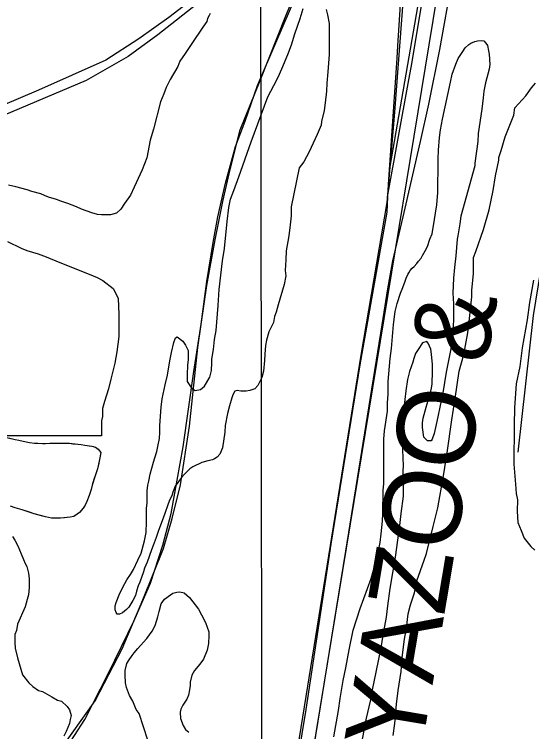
# Model space of a CAD drawing. Extents: x 3313442 to 3351311, y 721974 to 747360.
# Drawn here: x 3327806 to 3328357, y 731523 to 732286 of the extents above; entities that cross this region are included whole.
import ezdxf

# ---------------------------------------------------------------- set-up
doc = ezdxf.new("R2010")
doc.units = 0
for name, color, linetype in [('V-GRID-MAJR', 7, 'Continuous'), ('V-RAIL-IDEN', 7, 'Continuous'), ('V-RAIL-TRAK', 7, 'Continuous'), ('V-ROAD-CNTR', 7, 'Continuous'), ('V-SITE-VEGE', 7, 'Continuous'), ('V-TOPO-SHOR', 7, 'Continuous')]:
    doc.layers.add(name, color=color, linetype=linetype)

msp = doc.modelspace()

# ---------------------------------------------------------------- linework, layer by layer
at = {"layer": 'V-GRID-MAJR'}
msp.add_spline([(3328075.07, 727366.28), (3328067.14, 733424.95), (3328059.2, 739486.71), (3328051.27, 745548.49), (3328051.26, 745551.55)], degree=3, dxfattribs=at)
at = {"layer": 'V-RAIL-TRAK'}
for points in [[(3328203.52, 732092.24), (3328226.38, 732216.75), (3328228.79, 732229.89), (3328244.41, 732323.62), (3328261.52, 732426.58), (3328323.27, 732818.5), (3328429.42, 733429.55), (3328523.11, 733982.36), (3328555.08, 734220.1)], [(3328500.98, 734062.08), (3328491.15, 734030.23), (3328478.19, 734001.71), (3328469.68, 733983.34), (3328457.58, 733940.94), (3328295.7, 733004.83), (3328243.2, 732687.44), (3328233.88, 732532.71), (3328228.65, 732476.24), (3328224.01, 732410.03), (3328223.76, 732406.49), (3328219.24, 732330.46), (3328214.34, 732252.95), (3328213.43, 732239.7)], [(3328193.53, 732625.7), (3328177.22, 732567.4), (3328169.07, 732540.83), (3328156.85, 732510.58), (3328143.9, 732481.07), (3328134.65, 732462.26), (3328103.21, 732412.1), (3328071.41, 732367.84), (3328040.36, 732333.56), (3328005.63, 732301.12), (3327959.07, 732264.63), (3327927.3, 732241.42), (3327882.61, 732216.01), (3327776.62, 732171.47), (3327637.03, 732113.33), (3327497.8, 732056.29), (3327254.9, 731954.47)], [(3327916.04, 730340.51), (3327940.55, 730453.8), (3327956.49, 730526.28), (3327968.38, 730580.36), (3327984, 730670.04), (3328012.27, 730843.85), (3328056.88, 731105.86), (3328114.88, 731442.42), (3328159.14, 731715.13), (3328197.82, 731956.11), (3328203.77, 731994.12), (3328209.35, 732024.01), (3328220.11, 732070.88), (3328238.67, 732150.95), (3328247.57, 732190.8), (3328259.09, 732249.11), (3328272.47, 732322.54), (3328282.13, 732380.48), (3328307.79, 732543.91)], [(3327859.42, 731501.7), (3327881.24, 731536), (3327906.4, 731585.06), (3327933.78, 731641.13), (3327951.18, 731680.98), (3327964.15, 731721.56), (3327973.05, 731755.14), (3327986.05, 731825.99), (3327997.23, 731906.44), (3328005.04, 731956.63), (3328011, 732002.03), (3328018.07, 732043.73), (3328022.9, 732071.03), (3328031.06, 732106.83), (3328041.81, 732145.94), (3328051.82, 732172.87), (3328065.15, 732210.87), (3328084.77, 732256.25), (3328106.98, 732308.27)], [(3328213.43, 732239.7), (3328204.2, 732105.32), (3328203.52, 732092.24)], [(3328203.52, 732092.24), (3328202.68, 732075.79), (3328174.06, 731913.42), (3328143.19, 731722.63), (3328116.4, 731546.6), (3328078.46, 731315.59), (3327969.89, 730676.8), (3327964.29, 730653.18)]]:
    msp.add_lwpolyline(points, dxfattribs=at)
at = {"layer": 'V-ROAD-CNTR'}
for points in [[(3327896.37, 730170.39), (3328023.81, 730890.68), (3328416, 733278.4), (3328655.93, 734782.08)], [(3327962.42, 730543.73), (3327970.46, 730696.77), (3327985.73, 730796.82), (3328034.34, 731082.14), (3328099.58, 731452.49), (3328175.49, 731923.72), (3328203.27, 732086.22), (3328211.41, 732182.17), (3328220.63, 732304.33), (3328231.12, 732438.59), (3328237.49, 732535.43), (3328252.25, 732631.39), (3328363.9, 733327.81), (3328438.61, 733764.24), (3328463.17, 733920.78), (3328473.54, 733984.22), (3328487.83, 734056.22), (3328522.06, 734173.98), (3328557.71, 734288.4), (3328569.15, 734337.69), (3328584.55, 734386.98), (3328603.76, 734460.3)], [(3328206.53, 732124.57), (3328291.9, 732618.44), (3328336.97, 732892.88), (3328390.91, 733218.11), (3328451.63, 733573.02), (3328572.2, 734347.47)], [(3328383.21, 733788.69), (3328352.42, 733597.3), (3328320.34, 733409.27), (3328290.34, 733234.13), (3328260.68, 733052.87), (3328231.63, 732880.48), (3328210.69, 732738.01), (3328196.79, 732652.65), (3328178.86, 732577.61), (3328159.51, 732521.03), (3328133.66, 732473.03), (3328100.17, 732414.66), (3328072.81, 732378.12), (3328040.68, 732341.05), (3328010.44, 732313.92), (3327970.59, 732283.17), (3327938.89, 732260.24), (3327903.72, 732237.86), (3327832.02, 732205.9), (3327553.19, 732087.35)], [(3327852.97, 731500.25), (3327892.13, 731555.88), (3327921.14, 731611.05), (3327943.08, 731663.12), (3327964.98, 731718.01), (3327974.2, 731749.83), (3327982.95, 731785.8), (3327992.77, 731847.98), (3328001.47, 731931.94), (3328011.09, 731997.78), (3328020.08, 732046.53), (3328028.07, 732087.12), (3328036.17, 732121.46), (3328046.78, 732163.56), (3328067.83, 732216.06), (3328095.32, 732284.89), (3328118.41, 732340.46), (3328137.25, 732395.18), (3328158.23, 732451.12), (3328167.74, 732497.32), (3328194.11, 732641.44)]]:
    msp.add_lwpolyline(points, dxfattribs=at)
at = {"layer": 'V-SITE-VEGE'}
for points in [[(3327973.37, 731926.57), (3327975.85, 731937.29), (3327977.78, 731941.96), (3327979.71, 731943.33), (3327985.75, 731938.65), (3327988.5, 731934.25), (3327991.24, 731928.47), (3327991.23, 731918.58), (3327990.4, 731913.35), (3327990.11, 731902.63), (3327990.37, 731895.49), (3327995.04, 731888.06), (3327998.61, 731886.13), (3328004.38, 731887.22), (3328008.79, 731890.79), (3328014.3, 731900.13), (3328016.23, 731907.27), (3328016.51, 731915.52), (3328016.52, 731919.09), (3328017.07, 731923.77), (3328018.18, 731929.54), (3328019.29, 731940.53), (3328020.95, 731949.88), (3328023.18, 731976.54), (3328024.31, 731993.58), (3328027.92, 732024.09), (3328029.85, 732037.28), (3328032.64, 732065.87), (3328034.58, 732080.71), (3328036.52, 732089.78), (3328039.83, 732099.12), (3328045.06, 732113.41), (3328058.31, 732150.78), (3328076.23, 732198.59), (3328082.57, 732210.68), (3328086.98, 732219.47), (3328090.84, 732228.54), (3328097.45, 732243.65), (3328101.31, 732254.09), (3328104.9, 732265.63), (3328110.69, 732282.11), (3328113.73, 732292.56)], [(3328138.19, 732291.7), (3328139.56, 732285.93), (3328141.48, 732276.86), (3328141.44, 732243.87), (3328140.04, 732225.18), (3328138.93, 732213.08), (3328138.64, 732204.56), (3328136.98, 732192.19), (3328136.14, 732183.95), (3328133.38, 732172.41), (3328132.82, 732168.56), (3328128.69, 732158.67), (3328120.15, 732140.26), (3328114.36, 732129.55), (3328109.4, 732122.95), (3328101.11, 732081.73)], [(3328014.84, 732287.51), (3328013.62, 732285.08), (3328011.79, 732282.04), (3328011.18, 732278.99), (3328006.92, 732272.92), (3327995.33, 732255.29), (3327988.02, 732244.95), (3327982.53, 732236.45), (3327980.1, 732230.97), (3327972.17, 732216.99), (3327967.9, 732208.47), (3327965.46, 732201.79), (3327961.8, 732193.27), (3327954.46, 732164.08), (3327950.8, 732152.53), (3327947.13, 732133.67), (3327942.24, 732120.9), (3327933.7, 732102.66), (3327930.04, 732094.15), (3327923.34, 732085.03), (3327919.68, 732078.95), (3327914.81, 732074.7), (3327908.72, 732072.88), (3327898.99, 732072.89), (3327894.73, 732073.51), (3327888.65, 732075.34), (3327877.71, 732079), (3327872.23, 732081.44), (3327863.11, 732085.1), (3327855.81, 732087.55), (3327850.95, 732089.38), (3327842.43, 732091.82), (3327838.18, 732093.65), (3327834.53, 732095.48), (3327824.8, 732097.92), (3327819.94, 732099.76), (3327807.77, 732102.81), (3327799.86, 732104.65)], [(3328146.33, 731517.32), (3328151.32, 731545.35), (3328153.25, 731558.27), (3328156.3, 731577.23), (3328159.07, 731590.97), (3328162.66, 731609.94), (3328167.09, 731630.82), (3328174.26, 731654.18), (3328186.12, 731686.05), (3328193.02, 731710.24), (3328195.79, 731724.25), (3328196.9, 731733.6), (3328198.29, 731747.06), (3328198.58, 731755.04), (3328198.59, 731765.76), (3328198.87, 731769.33), (3328198.88, 731779.78), (3328199.44, 731787.2), (3328199.73, 731797.92), (3328199.75, 731814.69), (3328199.48, 731820.74), (3328199.5, 731834.2), (3328200.33, 731843.28), (3328203.38, 731864.17), (3328203.66, 731872.96), (3328204.23, 731882.03), (3328204.24, 731895.5), (3328206.47, 731920.24), (3328207.86, 731930.69), (3328209.81, 731956.25), (3328211.75, 731970.26), (3328213.69, 731978.51), (3328217.27, 731989.78), (3328219.76, 731995.82), (3328222.24, 732002.41), (3328223.34, 732005.71), (3328225.27, 732009.56), (3328226.1, 732011.48), (3328227.75, 732013.68), (3328229.95, 732016.15), (3328231.88, 732018.07), (3328234.63, 732021.09), (3328236.56, 732023.84), (3328239.31, 732026.86), (3328240.96, 732029.6), (3328243.72, 732034.83), (3328245.93, 732039.5), (3328248.68, 732047.19), (3328251.16, 732052.69), (3328253.66, 732068.08), (3328254.49, 732074.67), (3328255.87, 732083.74), (3328256.99, 732096.66), (3328257, 732108.48), (3328257.29, 732118.38), (3328257.31, 732132.67), (3328257.87, 732142.02), (3328258.98, 732155.21), (3328260.09, 732163.46), (3328262.03, 732174.72), (3328270.6, 732214.3), (3328272.26, 732222.82), (3328276.12, 732233.26), (3328278.88, 732239.58), (3328283.56, 732247), (3328286.31, 732250.84), (3328290.17, 732254.41), (3328292.37, 732255.78), (3328296.49, 732257.43), (3328299.52, 732258.25), (3328303.64, 732258.52), (3328306.12, 732258.24), (3328308.31, 732255.76)], [(3328308.31, 732255.76), (3328309.96, 732253.29), (3328311.05, 732247.79), (3328311.6, 732243.94)], [(3328311.6, 732243.94), (3328312.41, 732232.94), (3328311.85, 732228.27), (3328307.98, 732213.43), (3328306.05, 732204.64), (3328305.22, 732197.49), (3328304.1, 732185.39), (3328300.22, 732159.56), (3328299.66, 732151.04), (3328296.34, 732127.95), (3328296.33, 732125.2), (3328281.7, 732071.62), (3328280.59, 732063.37), (3328279.76, 732059.25), (3328278.38, 732050.73), (3328277.55, 732047.15), (3328276.15, 732029.56), (3328274.76, 732016.92), (3328273.65, 732005.65), (3328273.08, 731989.71), (3328273.62, 731978.44), (3328273.87, 731960.84), (3328273.03, 731949.57), (3328271.64, 731933.91), (3328266.11, 731905.6), (3328262.51, 731883.61), (3328260.57, 731875.09), (3328256.15, 731853.1), (3328253.38, 731840.46), (3328251.18, 731834.42), (3328250.07, 731832.49), (3328246.23, 731832.5), (3328242.1, 731836.35), (3328240.74, 731846.53), (3328240.75, 731851.75), (3328241.58, 731856.7), (3328244.62, 731868.24), (3328246.83, 731875.38), (3328248.76, 731880.33), (3328250.42, 731888.57), (3328250.97, 731893.24), (3328251.54, 731906.17), (3328251.27, 731913.59), (3328250.46, 731924.86), (3328249.64, 731930.08), (3328246.9, 731936.41), (3328245.53, 731938.34), (3328240.85, 731936.69), (3328236.17, 731929.82), (3328233.42, 731925.43), (3328231.49, 731920.21), (3328230.66, 731916.09), (3328226.8, 731906.2), (3328224.86, 731897.95), (3328222.92, 731885.58), (3328221.81, 731876.51), (3328220.42, 731863.05), (3328219.58, 731852.05), (3328219.55, 731822.91), (3328220.08, 731805.87), (3328219.8, 731800.65), (3328220.05, 731784.7), (3328220.04, 731773.43), (3328217.54, 731755.29), (3328216.43, 731742.37), (3328211.71, 731708.57), (3328205.9, 731675.31), (3328203.4, 731656.89), (3328202.02, 731644.8), (3328198.69, 731625.56), (3328196.48, 731612.1), (3328190.95, 731586.26), (3328187.35, 731567.57), (3328185.14, 731555.48), (3328180.72, 731537.34), (3328175.46, 731509.31)], [(3328209.44, 731518.67), (3328211.28, 731531.44), (3328213.13, 731552.13), (3328214.98, 731566.72), (3328218.04, 731586.8), (3328219.28, 731602.01), (3328221.73, 731621.47), (3328223.57, 731633.03), (3328225.42, 731648.23), (3328227.86, 731657.96), (3328232.14, 731670.73), (3328234.58, 731683.51), (3328242.52, 731705.4), (3328244.96, 731712.7), (3328252.3, 731741.28), (3328257.19, 731761.35), (3328263.31, 731795.41), (3328266.99, 731819.74), (3328271.9, 731855.02), (3328275.58, 731877.53), (3328279.87, 731906.72), (3328284.76, 731924.36), (3328289.05, 731947.48), (3328290.89, 731962.68), (3328293.35, 731985.8), (3328293.36, 731992.49), (3328295.21, 732010.74), (3328295.23, 732027.77), (3328297.67, 732033.85), (3328305.61, 732057.57), (3328311.72, 732078.25), (3328316, 732098.93), (3328318.45, 732114.74), (3328322.12, 732131.16), (3328322.12, 732134.21), (3328324.57, 732141.5), (3328328.84, 732156.1), (3328338, 732179.21), (3328339.22, 732187.11), (3328350.8, 732199.88), (3328356.89, 732208.39), (3328361.16, 732213.25)], [(3328101.11, 732081.73), (3328101.1, 732078.43), (3328100.82, 732071.83), (3328099.98, 732062.49), (3328098.32, 732050.67), (3328095.55, 732034.73), (3328095.27, 732025.11), (3328094.7, 732013.84), (3328095.25, 732008.06), (3328093.58, 731998.72), (3328086.96, 731977.29), (3328085.03, 731969.59), (3328083.37, 731964.92), (3328081.99, 731958.6), (3328077.31, 731948.44), (3328074.54, 731939.64), (3328073.71, 731934.14), (3328072.88, 731924.8), (3328072.6, 731917.93), (3328071.48, 731906.66), (3328069.82, 731900.06), (3328065.41, 731891.27), (3328062.39, 731887.98), (3328056.89, 731886.06), (3328053.04, 731885.51), (3328047.27, 731885.52), (3328043.42, 731886.07), (3328040.94, 731885.53), (3328038.74, 731881.41), (3328037.91, 731878.11), (3328035.15, 731869.59), (3328033.22, 731861.62), (3328030.73, 731848.98), (3328030.17, 731841.56), (3328027.68, 731825.07), (3328024.92, 731818.47), (3328022.17, 731815.18), (3328019.14, 731813.26), (3328017.21, 731812.43), (3328012.27, 731811.34), (3328005.66, 731809.43), (3327996.31, 731804.76), (3327993.01, 731802.57), (3327987.51, 731797.08), (3327984.21, 731793.51), (3327977.6, 731784.17), (3327974.84, 731777.85), (3327973.73, 731774), (3327971.53, 731769.33), (3327964.63, 731750.1), (3327959.67, 731736.91), (3327957.19, 731729.49), (3327954.15, 731720.97), (3327952.22, 731716.3), (3327947.53, 731703.39), (3327944.78, 731696.79), (3327943.67, 731692.95), (3327939.81, 731681.95), (3327938.16, 731678.11), (3327936.23, 731672.34), (3327935.12, 731667.94), (3327932.37, 731662.44), (3327927.96, 731655.58), (3327925.76, 731652.83), (3327921.35, 731649.26), (3327918.33, 731647.89), (3327915.58, 731647.9), (3327914.48, 731649.82), (3327913.66, 731652.57), (3327913.66, 731656.7), (3327914.77, 731660.27), (3327917.8, 731668.51), (3327920.29, 731673.73), (3327923.87, 731680.6), (3327926.07, 731684.44), (3327929.93, 731690.21), (3327932.96, 731695.7), (3327937.64, 731705.32), (3327941.22, 731713.02), (3327944.81, 731726.2), (3327946.47, 731735), (3327947.04, 731746.27), (3327947.05, 731760.56), (3327947.61, 731766.61), (3327947.63, 731779.26), (3327948.46, 731785.3), (3327949.56, 731789.7), (3327950.67, 731797.12), (3327954.54, 731809.76), (3327955.64, 731814.43), (3327957.85, 731821.03), (3327958.95, 731826.52), (3327960.89, 731835.04), (3327961.17, 731841.36), (3327961.18, 731848.79), (3327962.58, 731868.31), (3327963.69, 731877.1), (3327966.73, 731892.21), (3327969.22, 731902.38), (3327971.71, 731917.5), (3327973.37, 731926.57)], [(3327798.82, 732044.8), (3327813.41, 732037.48), (3327819.49, 732035.04), (3327831.65, 732031.37), (3327840.17, 732028.32), (3327854.76, 732022.22), (3327885.77, 732010.02), (3327894.29, 732006.36), (3327900.37, 732003.31), (3327911.31, 731994.78), (3327916.77, 731984.43), (3327917.36, 731966.79), (3327917.33, 731943.67), (3327915.48, 731927.24), (3327913.04, 731915.08), (3327908.76, 731898.05), (3327906.31, 731887.71), (3327902.03, 731874.33), (3327900.2, 731867.03), (3327900.19, 731858.51), (3327898.97, 731853.65), (3327898.95, 731837.83), (3327786.77, 731837.97)], [(3328359.08, 732003.36), (3328354.79, 731979.64), (3328352.34, 731961.39), (3328346.82, 731931.59), (3328344.37, 731911.52), (3328340.69, 731893.27), (3328338.84, 731867.72), (3328338.21, 731849.47), (3328338.16, 731807.49), (3328339.96, 731786.2), (3328340.55, 731776.46), (3328341.76, 731769.77), (3328341.75, 731757.6), (3328342.34, 731745.43), (3328345.98, 731736.91), (3328349.01, 731729), (3328356.3, 731719.86), (3328360.56, 731716.21)], [(3327794.9, 731836.63), (3327806.92, 731834.06), (3327810.86, 731833.07), (3327818.93, 731831.48), (3327822.28, 731830.69), (3327827.6, 731830.09), (3327836.27, 731829.68), (3327839.42, 731829.68), (3327848.49, 731830.06), (3327861.69, 731830.05), (3327865.04, 731829.84), (3327873.91, 731828.85), (3327877.26, 731828.65), (3327881.2, 731828.05), (3327888.88, 731826.67), (3327892.62, 731825.68), (3327895.58, 731823.7), (3327898.13, 731820.15), (3327896.94, 731812.66), (3327894.76, 731802.62), (3327892.19, 731795.13), (3327889.03, 731785.29), (3327887.84, 731780.76), (3327885.86, 731774.45), (3327883.49, 731767.95), (3327881.71, 731764.01), (3327879.34, 731760.67), (3327875.59, 731756.33), (3327873.03, 731754.37), (3327869.68, 731752.01), (3327865.73, 731751.22), (3327855.49, 731750.25), (3327845.63, 731750.26), (3327839.53, 731751.45), (3327827.31, 731754.62), (3327814.51, 731759.17), (3327807.02, 731761.34), (3327802.1, 731763.12)], [(3327804.28, 731730.49), (3327806.71, 731726.84), (3327809.74, 731720.75), (3327813.38, 731712.23), (3327815.81, 731706.14), (3327817.63, 731701.88), (3327819.45, 731698.84), (3327821.27, 731691.54), (3327821.87, 731685.45), (3327821.86, 731676.33)], [(3327821.86, 731676.33), (3327821.24, 731668.42), (3327820.02, 731663.55), (3327817.57, 731655.65), (3327809.64, 731637.41), (3327808.42, 731630.71), (3327806.59, 731626.46), (3327806.58, 731617.94), (3327807.18, 731611.86), (3327809.6, 731601.51), (3327815.05, 731583.25), (3327821.73, 731574.73), (3327825.99, 731571.07), (3327832.07, 731566.81), (3327836.33, 731565.59), (3327846.05, 731560.1), (3327852.13, 731556.44), (3327856.39, 731555.22), (3327862.47, 731549.74), (3327864.9, 731546.08), (3327866.71, 731540), (3327865.49, 731535.74), (3327864.88, 731531.48), (3327861.22, 731522.97), (3327858.78, 731518.11)], [(3327953.06, 731499.68), (3327939.09, 731542.31), (3327936.08, 731546.44), (3327932.24, 731555.23), (3327928.67, 731561.56), (3327925.66, 731570.09), (3327924.56, 731575.04), (3327924.02, 731583.01), (3327924.03, 731587.96), (3327925.96, 731595.38), (3327928.44, 731599.5), (3327931.75, 731604.17), (3327933.95, 731606.91), (3327937.8, 731611.31), (3327943.86, 731618.17), (3327947.44, 731622.02), (3327952.94, 731629.98), (3327955.97, 731635.75), (3327959.01, 731645.09), (3327960.39, 731650.86), (3327962.6, 731659.11), (3327966.18, 731664.05), (3327972.51, 731668.72), (3327974.98, 731670.37), (3327979.38, 731671.46), (3327982.41, 731671.73), (3327987.08, 731670.62), (3327992.85, 731665.67), (3328002.18, 731653.29), (3328005.47, 731647.24), (3328009.58, 731639.26), (3328013.14, 731629.09), (3328013.41, 731625.24), (3328012.85, 731616.72), (3328011.47, 731609.57), (3328007.61, 731599.95), (3328003.75, 731594.73), (3327997.98, 731587.87), (3327995.22, 731582.92), (3327993.29, 731575.5), (3327993.28, 731571.93), (3327992.73, 731567.53), (3327991.62, 731561.76), (3327989.69, 731557.64), (3327985.56, 731551.05), (3327983.63, 731546.93), (3327982.8, 731543.63), (3327983.07, 731537.03), (3327985.81, 731529.61), (3327988.55, 731525.2), (3327992.12, 731522.45)]]:
    msp.add_lwpolyline(points, dxfattribs=at)
at = {"layer": 'V-TOPO-SHOR'}
for points in [[(3328287.65, 732336.47), (3328431.83, 732347.8), (3328395.47, 732192.26), (3328358.68, 731966.06), (3328342.31, 731820.32)], [(3327801.4, 731835.24), (3327806.92, 731834.06), (3327810.86, 731833.07), (3327814.01, 731832.47), (3327818.93, 731831.48), (3327822.28, 731830.69), (3327827.6, 731830.09), (3327831.15, 731829.89), (3327836.27, 731829.68), (3327839.42, 731829.68), (3327843.96, 731829.87), (3327848.49, 731830.06), (3327852.04, 731830.06), (3327857.95, 731830.05), (3327861.69, 731830.05), (3327865.04, 731829.85), (3327868.59, 731829.45), (3327873.91, 731828.85), (3327877.26, 731828.65), (3327881.2, 731828.05), (3327885.73, 731827.26), (3327888.88, 731826.67), (3327892.62, 731825.68), (3327895.58, 731823.7), (3327898.13, 731820.15), (3327897.54, 731816.02), (3327896.94, 731812.66), (3327895.75, 731806.95), (3327894.76, 731802.62), (3327892.19, 731795.13), (3327891, 731791.39), (3327889.03, 731785.29), (3327887.84, 731780.76), (3327885.86, 731774.45), (3327883.49, 731767.95), (3327881.71, 731764.01), (3327879.34, 731760.67), (3327875.59, 731756.33), (3327873.03, 731754.37), (3327869.68, 731752.01), (3327865.73, 731751.22), (3327859.62, 731750.64), (3327855.49, 731750.25), (3327849.38, 731750.26), (3327845.63, 731750.26), (3327839.53, 731751.45), (3327835, 731752.64), (3327827.31, 731754.62), (3327822.19, 731756.4), (3327814.51, 731759.17), (3327807.02, 731761.34), (3327802.1, 731763.12)]]:
    msp.add_lwpolyline(points, dxfattribs=at)

# ---------------------------------------------------------------- texts
at = {"layer": 'V-RAIL-IDEN'}
msp.add_text('(YAZOO &', height=83, rotation=80.47014, dxfattribs=at).set_placement((3328233.02, 731462.66))

doc.saveas('drawing.dxf')
